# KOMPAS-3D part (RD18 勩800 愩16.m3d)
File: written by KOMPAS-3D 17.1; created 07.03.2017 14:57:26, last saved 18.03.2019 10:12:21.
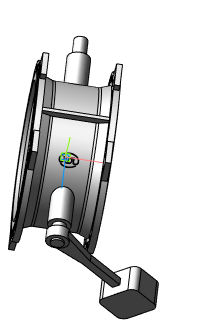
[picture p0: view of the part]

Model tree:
1. Операция без истории:2  (labels: Сталь 20  ГОСТ 1050-88)

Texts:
  RD18 Ду100 Ру16
  RD18 Ду150 Ру16
  RD18 Ду200 Ру16
  RD18 Ду250 Ру16
  RD18 Ду300 Ру16
  RD18 Ду350 Ру16
  RD18 Ду400 Ру10
  RD18 Ду400 Ру16
  RD18 Ду450 Ру10
  RD18 Ду450 Ру16
  RD18 Ду500 Ру10
  RD18 Ду500 Ру16
  RD18 Ду600 Ру10
  RD18 Ду600 Ру16
  RD18 Ду700 Ру10
  RD18 Ду700 Ру16
  RD18 Ду800 Ру10
  RD18 Ду800 Ру16
  RD18 Ду900 Ру10
  RD18 Ду900 Ру16
  RD18 Ду1000 Ру10
  RD18 Ду1000 Ру16
  RD18 Ду1200 Ру16
  RD18 Ду1400 Ру16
